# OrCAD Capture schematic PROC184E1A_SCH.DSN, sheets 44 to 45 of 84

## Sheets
44 48. DUAL PORT FTDI: size C; title: DUAL PORT FTDI; note: PROC184_SCH
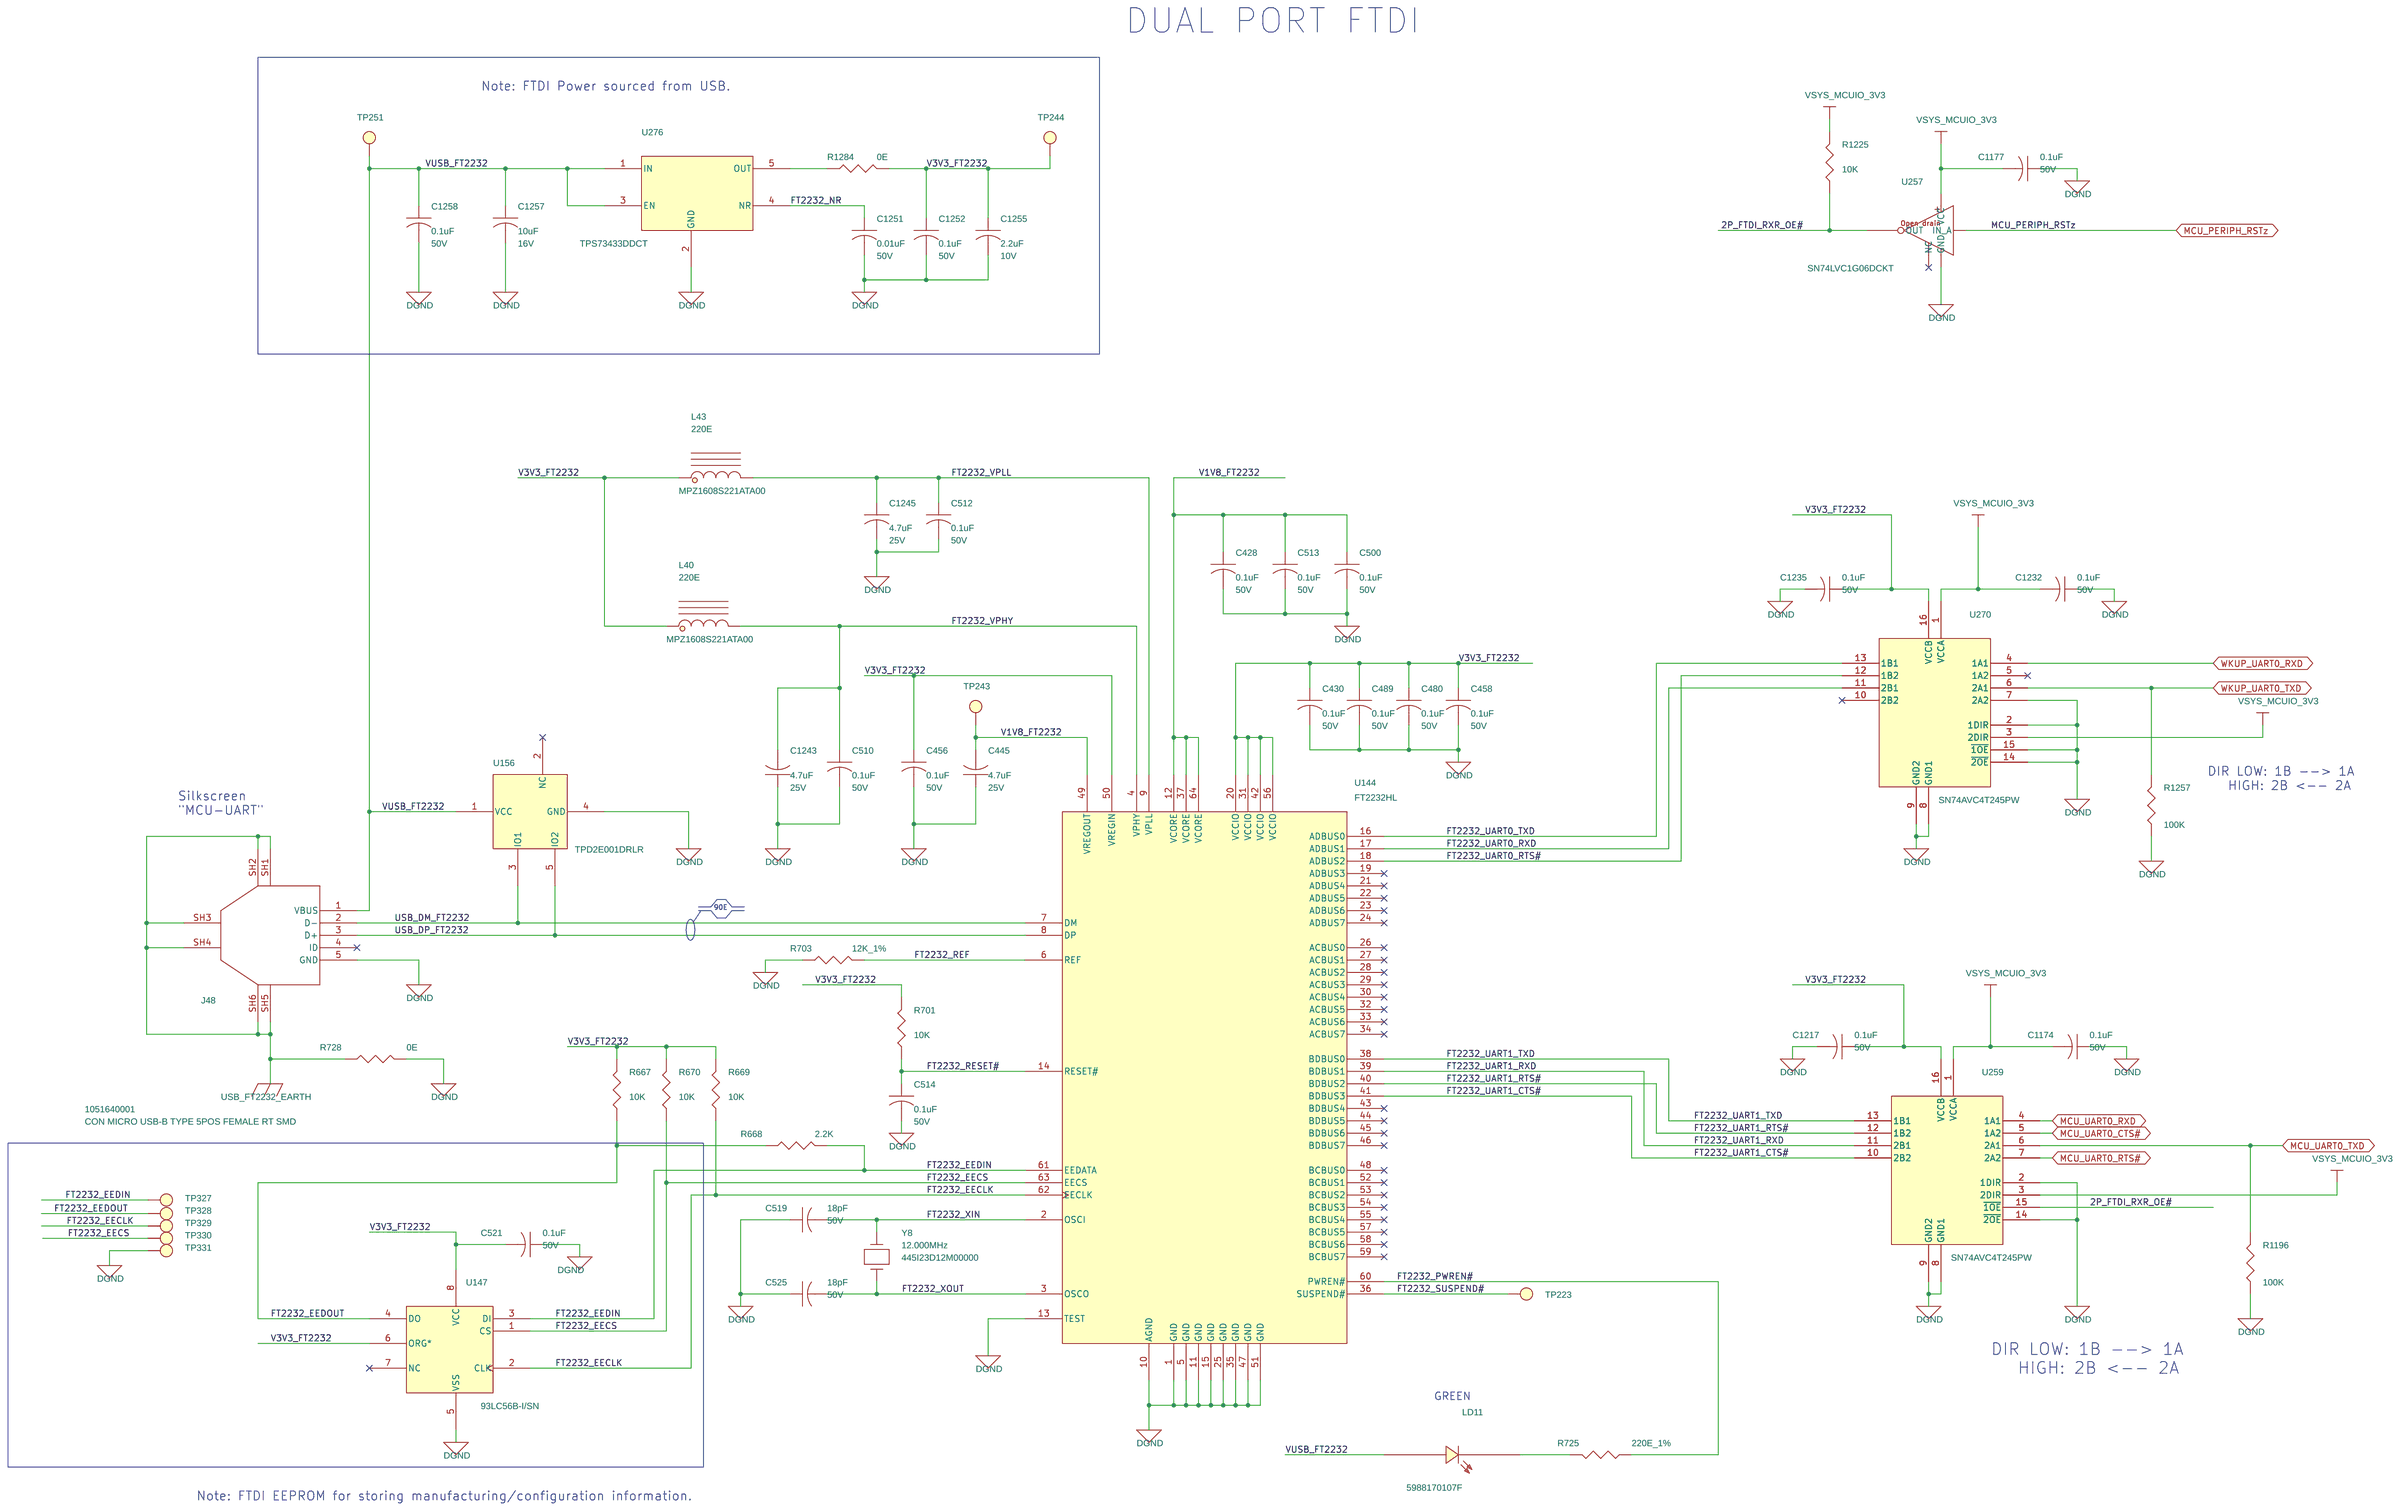
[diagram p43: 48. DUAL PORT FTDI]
45 49. QUAD PORT FTDI: size C; title: QUAD PORT FTDI; note: PROC184_SCH
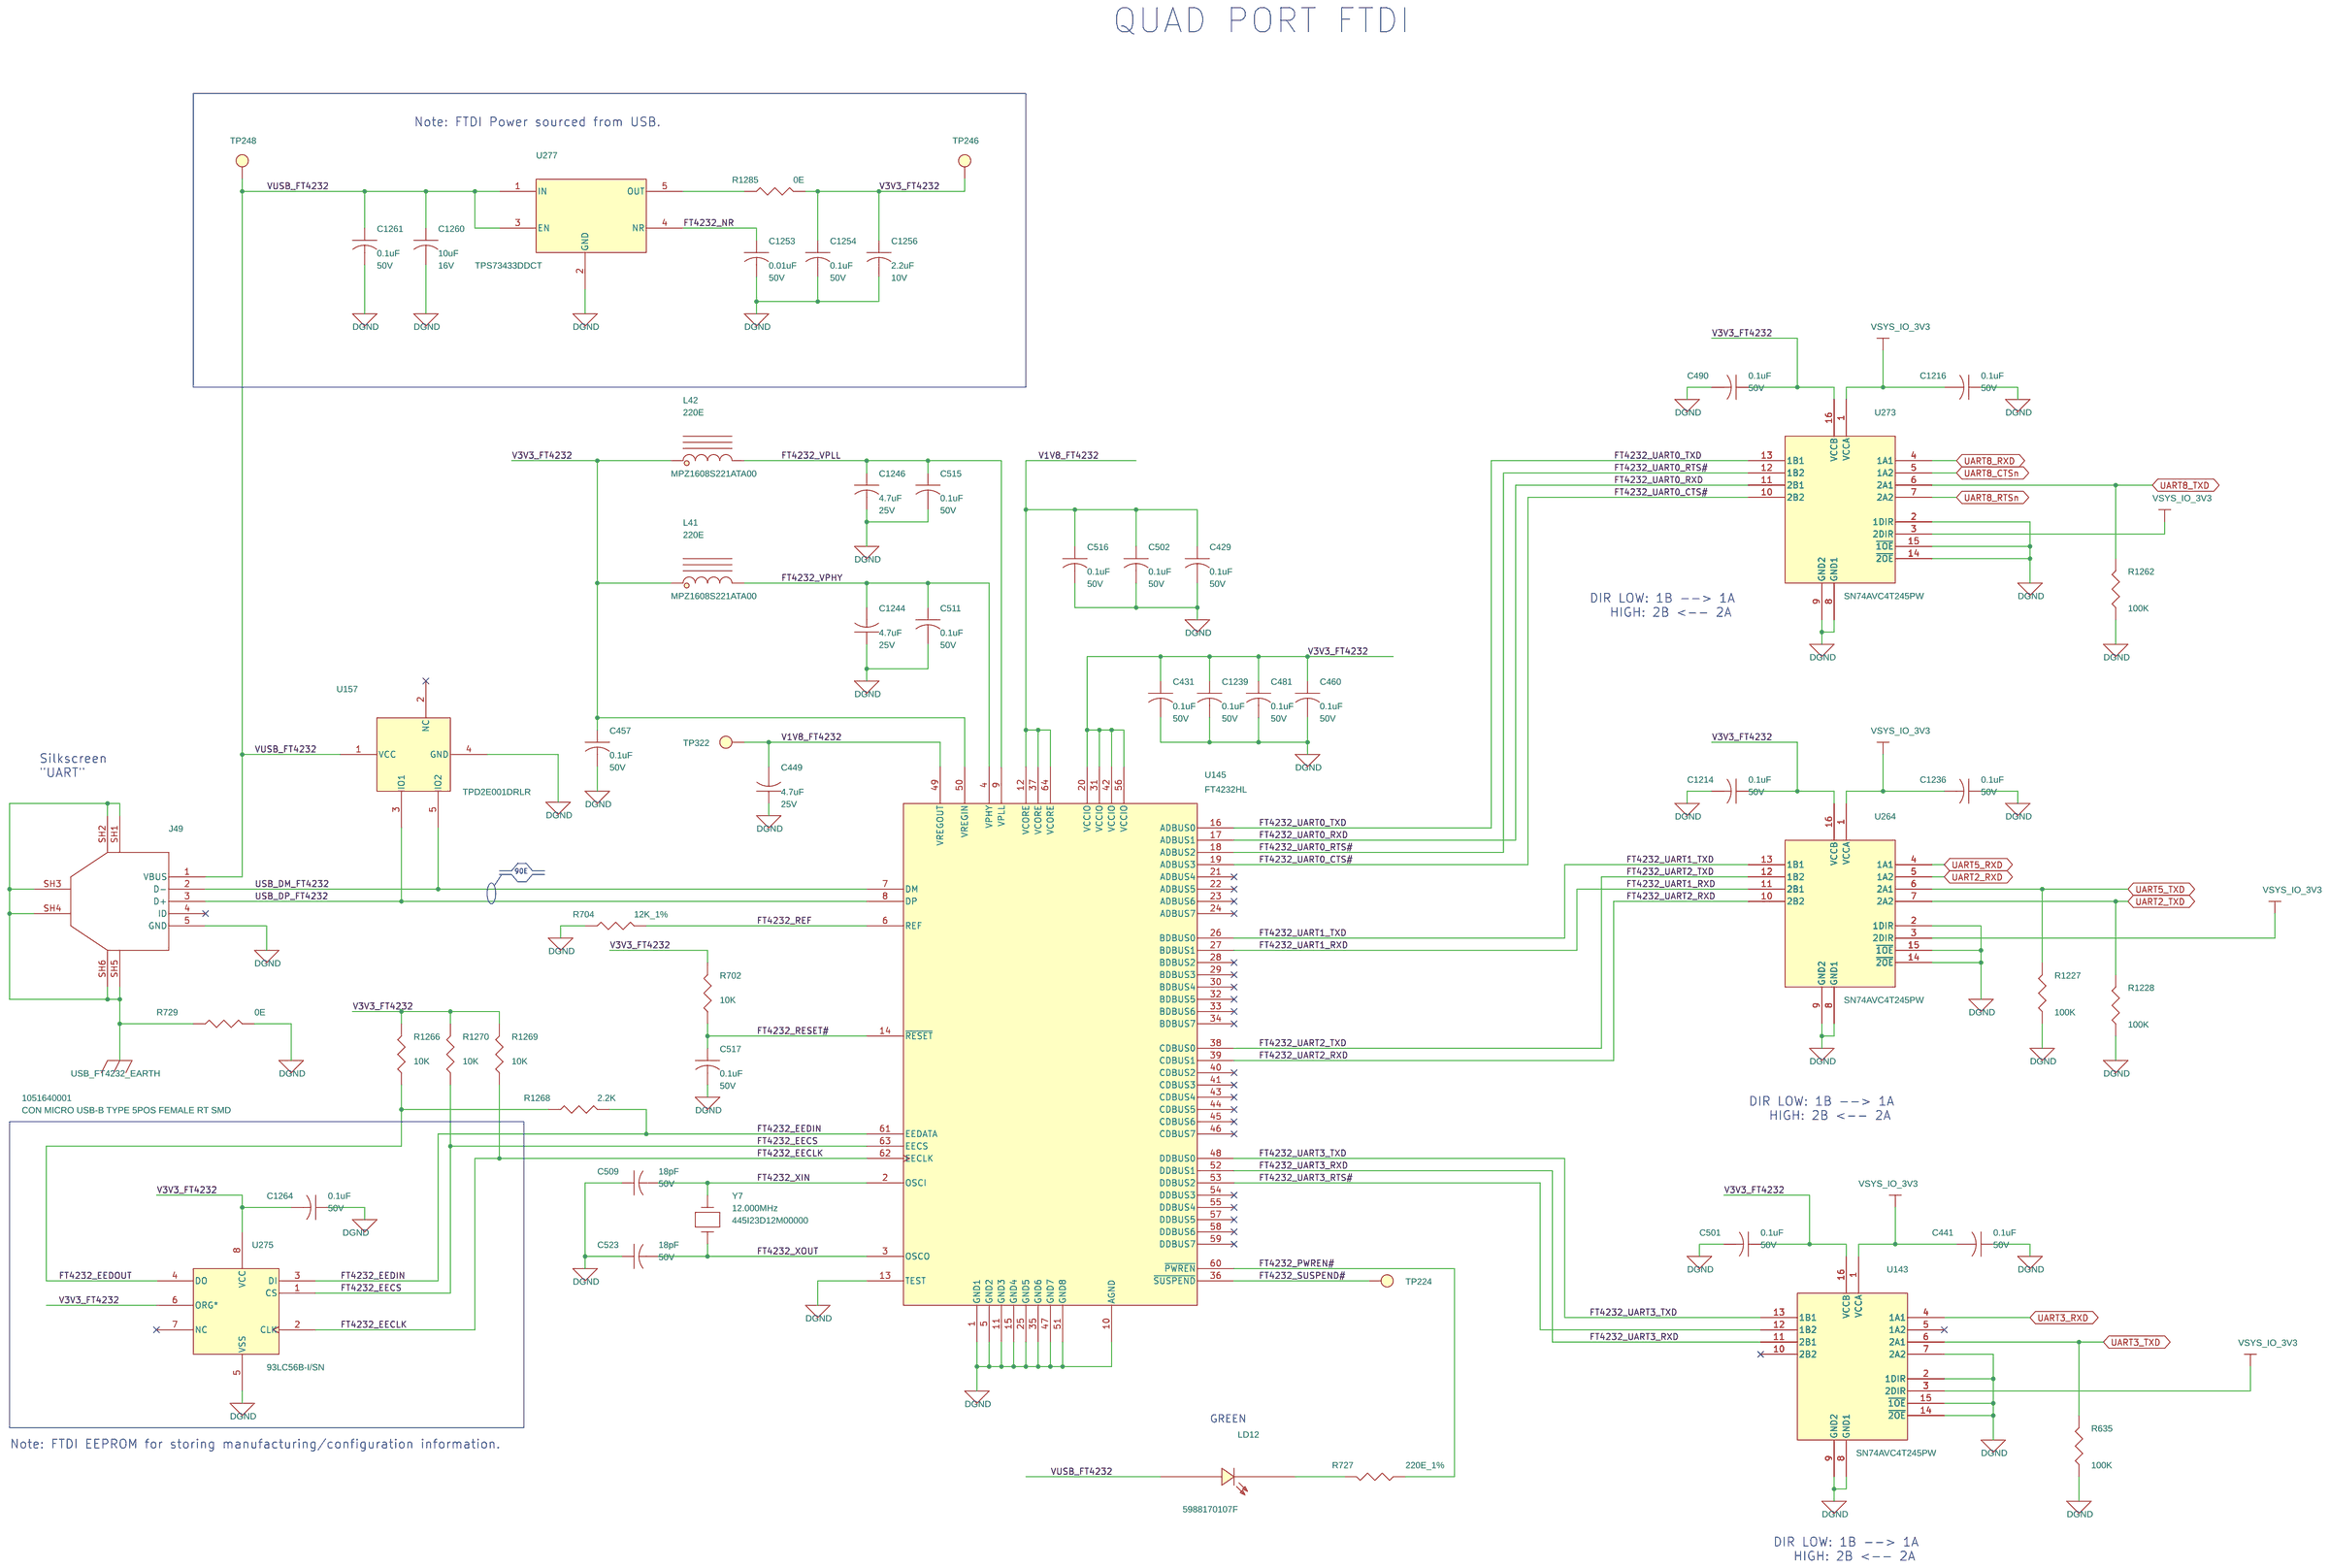
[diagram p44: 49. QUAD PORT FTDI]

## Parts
sheet 48. DUAL PORT FTDI
C428  0.1uF  [CAP0402_0-75]
C430  0.1uF  [CAP0402_0-75]
C445  4.7uF  [CAP0603_1]
C456  0.1uF  [CAP0402_0-75]
C458  0.1uF  [CAP0402_0-75]
C480  0.1uF  [CAP0402_0-75]
C489  0.1uF  [CAP0402_0-75]
C500  0.1uF  [CAP0402_0-75]
C510  0.1uF  [CAP0402_0-75]
C512  0.1uF  [CAP0402_0-75]
C513  0.1uF  [CAP0402_0-75]
C514  0.1uF  [CAP0402_0-75]
C519  18pF  [CAP0402_0-75]
C521  0.1uF  [CAP0402_0-75]
C525  18pF  [CAP0402_0-75]
C1174  0.1uF  [CAP0402_0-75]
C1177  0.1uF  [CAP0402_0-75]
C1217  0.1uF  [CAP0402_0-75]
C1232  0.1uF  [CAP0402_0-75]
C1235  0.1uF  [CAP0402_0-75]
C1243  4.7uF  [CAP0603_1]
C1245  4.7uF  [CAP0603_1]
C1251  0.01uF  [CAP0402_0-75]
C1252  0.1uF  [CAP0402_0-75]
C1255  2.2uF  [CAP0402_0-75]
C1257  10uF  [CAP0805_1-5]
C1258  0.1uF  [CAP0402_0-75]
J48  CON_MUSB-B_5_F  [CON_MUSBB5_1051640001_S_R_S_2-5]
L40  220E  [IND0603_1]
L43  220E  [IND0603_1]
LD11  5988170107F  [LED_0805_0-7]
R667  10K  [RES0402_0-5]
R668  2.2K  [RES0402_0-5]
R669  10K  [RES0402_0-5]
R670  10K  [RES0402_0-5]
R701  10K  [RES0402_0-5]
R703  12K_1%  [RES0402_0-5]
R725  220E_1%  [RES0402_0-5]
R728  0E  [RES0805_0-75]
R1196  100K  [RES0402_0-5]
R1225  10K  [RES0402_0-5]
R1257  100K  [RES0402_0-5]
R1284  0E  [RES0402_0-5]
TP223  TP30_SMD  [TP30_SMD]
TP243  THRU HOLE  [TP_40X65]
TP244  THRU HOLE  [TP_40X65]
TP251  THRU HOLE  [TP_40X65]
TP327  THRU HOLE  [TP_40X65]
TP328  THRU HOLE  [TP_40X65]
TP329  THRU HOLE  [TP_40X65]
TP330  THRU HOLE  [TP_40X65]
TP331  THRU HOLE  [TP_40X65]
U144  FT2232HL  [LQFP64_19-68_400X400_1-6]
U147  93LC56B-I/SN  [SOIC8]
U156  TPD2E001DRLR  [SOT553-5_0-6]
U257  SN74LVC1G06DCKT  [SC70-5_1-1]
U259  SN74AVC4T245PW  [TSSOP16_25-59_205X180]
U270  SN74AVC4T245PW  [TSSOP16_25-59_205X180]
U276  TPS73433DDCT  [SOT23-5_1-1]
Y8  12.000MHz  [XTAL_ABM3_205X130_SMD_1-4]
sheet 49. QUAD PORT FTDI
C429  0.1uF  [CAP0402_0-75]
C431  0.1uF  [CAP0402_0-75]
C441  0.1uF  [CAP0402_0-75]
C449  4.7uF  [CAP0603_1]
C457  0.1uF  [CAP0402_0-75]
C460  0.1uF  [CAP0402_0-75]
C481  0.1uF  [CAP0402_0-75]
C490  0.1uF  [CAP0402_0-75]
C501  0.1uF  [CAP0402_0-75]
C502  0.1uF  [CAP0402_0-75]
C509  18pF  [CAP0402_0-75]
C511  0.1uF  [CAP0402_0-75]
C515  0.1uF  [CAP0402_0-75]
C516  0.1uF  [CAP0402_0-75]
C517  0.1uF  [CAP0402_0-75]
C523  18pF  [CAP0402_0-75]
C1214  0.1uF  [CAP0402_0-75]
C1216  0.1uF  [CAP0402_0-75]
C1236  0.1uF  [CAP0402_0-75]
C1239  0.1uF  [CAP0402_0-75]
C1244  4.7uF  [CAP0603_1]
C1246  4.7uF  [CAP0603_1]
C1253  0.01uF  [CAP0402_0-75]
C1254  0.1uF  [CAP0402_0-75]
C1256  2.2uF  [CAP0402_0-75]
C1260  10uF  [CAP0805_1-5]
C1261  0.1uF  [CAP0402_0-75]
C1264  0.1uF  [CAP0402_0-75]
J49  CON_MUSB-B_5_F  [CON_MUSBB5_1051640001_S_R_S_2-5]
L41  220E  [IND0603_1]
L42  220E  [IND0603_1]
LD12  5988170107F  [LED_0805_0-7]
R635  100K  [RES0402_0-5]
R702  10K  [RES0402_0-5]
R704  12K_1%  [RES0402_0-5]
R727  220E_1%  [RES0402_0-5]
R729  0E  [RES0805_0-75]
R1227  100K  [RES0402_0-5]
R1228  100K  [RES0402_0-5]
R1262  100K  [RES0402_0-5]
R1266  10K  [RES0402_0-5]
R1268  2.2K  [RES0402_0-5]
R1269  10K  [RES0402_0-5]
R1270  10K  [RES0402_0-5]
R1285  0E  [RES0402_0-5]
TP224  TP30_SMD  [TP30_SMD]
TP246  THRU HOLE  [TP_40X65]
TP248  THRU HOLE  [TP_40X65]
TP322  TP30_SMD  [TP30_SMD]
U143  SN74AVC4T245PW  [TSSOP16_25-59_205X180]
U145  FT4232HL  [LQFP64_19-68_390X390_1-6]
U157  TPD2E001DRLR  [SOT553-5_0-6]
U264  SN74AVC4T245PW  [TSSOP16_25-59_205X180]
U273  SN74AVC4T245PW  [TSSOP16_25-59_205X180]
U275  93LC56B-I/SN  [SOIC8]
U277  TPS73433DDCT  [SOT23-5_1-1]
Y7  12.000MHz  [XTAL_ABM3_205X130_SMD_1-4]

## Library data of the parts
C428-C431 C441 C456-C458 C460 C480 C481 C489 C490 C500-C502 C510-C517 C521 C1174 C1177 C1214 C1216 C1217 C1232 C1235 C1236 C1239 C1252 C1254 C1258 C1261 C1264 = CAP: CAP CERAMIC 0.1uF 50V 10% X7R 0402; Automotive Alternate_mfr_name: TDK; Automotive Alternate_mfr_part_number: CGA2B3X7R1H104K050BB; Chkd/date: MANIRAJA/261020; Crtd /date: ALVY/211020; Custom_Duty: 15%; Customs_HS_Code: 85322990; Direct Alternate_mfr_name: TDK; Direct Alternate_mfr_part_number: C1005X7R1H104K050BE; Distributor_name: DIGIKEY; Distributor_part_number: 490-10700-1-ND; Footprint Path: Y:\MIS_DATABASE\Library\ALTIUM_TOOL\PCB_FOOTPRINTS\Altium_Footprint_Lib.PcbLib; Height: 0.55MM; Library Path: Y:\MIS_DATABASE\Library\ALTIUM_TOOL\SCHEMATICS_PARTS\MS_DISCRETE_Library.schlib; Manufacturer: MURATA; Mfr_name: MURATA; Mfr_part_number: GRM155R71H104KE14D; Mistral Part No: 120011100014-R; Package: 0402; Part_type: CAPACITORS\CERAMIC; Project: J7_CP; RoHS: RoHS; Temperature: -55°C+125°C; Tolerance: 10%; Voltage: 50V; Wattage: NA; Weight: 3.1mg; Datasheet: Y:\MIS_DATABASE\DATASHEETS\CAPACITORS\GRM155R71H104KE14.PDF
C445 C449 C1243-C1246 = CAP: CAP CERAMIC 4.7uF 25V 10% X6S 0603; Chkd/date: MANIRAJA/241018; Crtd /date: ALVY/241018; Custom_Duty: 15%; Customs_HS_Code: 85322990; Direct Alternate_mfr_name: MURATA; Direct Alternate_mfr_part_number: GRM188C81E475ME11D; Distributor_name: DIGIKEY; Distributor_part_number: 490-7199-1-ND; Footprint Path: Y:\MIS_DATABASE\Library\ALTIUM_TOOL\PCB_FOOTPRINTS\Altium_Footprint_Lib.PcbLib; Height: 1.00MM; Library Path: Y:\MIS_DATABASE\Library\ALTIUM_TOOL\SCHEMATICS_PARTS\MS_DISCRETE_Library.schlib; Manufacturer: MURATA; Mfr_name: MURATA; Mfr_part_number: GRM188C81E475KE11D; Mistral Part No: 120018100056-R; Package: 0603; Part_type: CAPACITORS\CERAMIC; Project: TI_J7ES_EVM_CP; RoHS: RoHS; Temperature: -55°C+105°C; Tolerance: 10%; Voltage: 25V; Wattage: NA; Weight: 6.3mg; Datasheet: Y:\MIS_DATABASE\DATASHEETS\CAPACITORS\GRM188C81E475KE11D.PDF
C509 C519 C523 C525 = CAP: CAP CERAMIC 18pF 50V 5% HI-Q C0G(NP0) 0402; Automotive Alternate_mfr_name: TDK; Automotive Alternate_mfr_part_number: CGA2B2C0G1H180J050BA; Chkd/date: VASANTHA/030315; Crtd /date: NAVEED/271014; Custom_Duty: 15%; Customs_HS_Code: 85322990; Direct Alternate_mfr_name: KEMET; Direct Alternate_mfr_part_number: CBR04C180J5GAC; Distributor_name: DIGIKEY; Distributor_part_number: 490-3119-1-ND; Footprint Path: Y:\MIS_DATABASE\Library\ALTIUM_TOOL\PCB_FOOTPRINTS\Altium_Footprint_Lib.PcbLib; Height: 0.55MM; Library Path: Y:\MIS_DATABASE\Library\ALTIUM_TOOL\SCHEMATICS_PARTS\MS_DISCRETE_Library.schlib; Manufacturer: MURATA; Mfr_name: MURATA; Mfr_part_number: GJM1555C1H180JB01D; Mistral Part No: 120014100019-R; Package: 0402; Part_type: CAPACITORS\CERAMIC; Project: DC_MIST_RDC; RoHS: RoHS; Temperature: -55°C+125°C; Tolerance: 5%; Voltage: 50V; Wattage: NA; Weight: 6mg; Datasheet: Y:\MIS_DATABASE\DATASHEETS\CAPACITORS\MURATA-GXX-SER_NOV17.PDF
C1251 C1253 = CAP: CAP CERAMIC 0.01uF 50V 10% X7R 0402; Automotive Alternate_mfr_name: TDK; Automotive Alternate_mfr_part_number: CGA2B2X7R1E103K050BA; Chkd/date: MANIRAJA/280319; Crtd /date: MANIRAJA/280319; Custom_Duty: 15%; Customs_HS_Code: 85322990; Direct Alternate_mfr_name: YAGEO AMERICA; Direct Alternate_mfr_part_number: CC0402KRX7R8BB103; Distributor_name: DIGIKEY; Distributor_part_number: 490-4516-1-ND; Footprint Path: Y:\MIS_DATABASE\Library\ALTIUM_TOOL\PCB_FOOTPRINTS\Altium_Footprint_Lib.PcbLib; Height: 0.55MM; Library Path: Y:\MIS_DATABASE\Library\ALTIUM_TOOL\SCHEMATICS_PARTS\MS_DISCRETE_Library.schlib; Manufacturer: MURATA; Mfr_name: MURATA; Mfr_part_number: GRM155R71H103KA88D; Mistral Part No: 120009030025-R; Package: 0402; Part_type: CAPACITORS\CERAMIC; Project: G4_SVGA; RoHS: RoHS; Temperature: -55°C+125°C; Tolerance: 10%; Voltage: 50V; Wattage: NA; Weight: 0.65mg; Datasheet: Y:\MIS_DATABASE\DATASHEETS\CAPACITORS\GRM155R71H103KA88D.PDF
C1255 C1256 = CAP: CAP CERAMIC 2.2uF 10V 10% X5R 0402; Automotive Alternate_mfr_name: TAIYO YUDEN; Automotive Alternate_mfr_part_number: LMK105ABJ225MVHF; Chkd/date: MANIRAJA/251120; Crtd /date: ALVY/241120; Custom_Duty: 15%; Customs_HS_Code: 85322990; Direct Alternate_mfr_name: TDK; Direct Alternate_mfr_part_number: C1005X5R1A225K050BC; Distributor_name: MOUSER; Distributor_part_number: 81-GRM155R61A225K01D; Footprint Path: Y:\MIS_DATABASE\Library\ALTIUM_TOOL\PCB_FOOTPRINTS\Altium_Footprint_Lib.PcbLib; Height: 0.55MM; Library Path: Y:\MIS_DATABASE\Library\ALTIUM_TOOL\SCHEMATICS_PARTS\MS_DISCRETE_Library.schlib; Manufacturer: MURATA; Mfr_name: MURATA; Mfr_part_number: GRM155R61A225KE01D; Mistral Part No: 120011100038-R; Package: 0402; Part_type: CAPACITORS\CERAMIC; Project: PLCC_DIGITAL BRD PROTO; RoHS: RoHS; Temperature: -55°C+85°C; Tolerance: 10%; Voltage: 10V; Wattage: NA; Weight: 1.6mg; Datasheet: Y:\MIS_DATABASE\DATASHEETS\CAPACITORS\MURATA-GXX-SER_NOV17.PDF
C1257 C1260 = CAP: CAP CERAMIC 10uF 16V 10% X5R 0805; Automotive Alternate_mfr_name: TDK; Automotive Alternate_mfr_part_number: CGA4J1X7S1C106K125AC; Chkd/date: SHREESHAIL/220506; Crtd /date: MAZHAR/150506; Custom_Duty: 15%; Customs_HS_Code: 85322990; Direct Alternate_mfr_name: TDK; Direct Alternate_mfr_part_number: C2012X7S1C106K125AC; Distributor_name: DIGIKEY; Distributor_part_number: 490-3886-1-ND; Footprint Path: Y:\MIS_DATABASE\Library\ALTIUM_TOOL\PCB_FOOTPRINTS\Altium_Footprint_Lib.PcbLib; Height: 1.35MM; Library Path: Y:\MIS_DATABASE\Library\ALTIUM_TOOL\SCHEMATICS_PARTS\MS_DISCRETE_Library.schlib; Manufacturer: MURATA; Mfr_name: MURATA; Mfr_part_number: GRM21BR61C106KE15L; Mistral Part No: 120009030205-R; Package: 0805; Part_type: CAPACITORS\CERAMIC; Project: VOCERA; RoHS: RoHS; Temperature: -55°C+85°C; Tolerance: 10%; Voltage: 16V; Wattage: NA; Weight: 9.5mg; Datasheet: Y:\MIS_DATABASE\DATASHEETS\CAPACITORS\MURATA-GXX-SER_NOV17.PDF
J48 J49 = CON_MUSB-B_5_1051640001: CON MICRO USB-B TYPE 5POS FEMALE RT SMD; Chkd/date: MANIRAJA/230817; Crtd /date: MANIRAJA/230817; Custom_Duty: 24%; Customs_HS_Code: 85369090; Distributor_name: DIGIKEY; Distributor_part_number: WM11263CT-ND; Height: 2.45MM; Manufacturer: MOLEX; Mfr_name: MOLEX; Mfr_part_number: 1051640001; Mistral Part No: 150017080018-R; Package: SMD; Part_type: CONNECTOR\USB; Project: TI_MAXIE_CPB; RoHS: RoHS; Temperature: -35°C+85°C; Tolerance: NA; Voltage: NA; Wattage: NA; Weight: 234mg; Datasheet: Y:\MIS_DATABASE\DATASHEETS\CONNECTORS\1051640001.PDF
L40-L43 = INDUCTOR_FERRITE: IND BEAD CHIP 220E 2.2A 25% 0603; Automotive Alternate_mfr_name: TDK; Automotive Alternate_mfr_part_number: MPZ1608S221ATD25; Chkd/date: MANIRAJA/130917; Crtd /date: USMAN/201108; Custom_Duty: 24%; Customs_HS_Code: 85437099; Direct Alternate_mfr_name: TDK; Direct Alternate_mfr_part_number: MPZ1608S221ATA00; Distributor_name: DIGIKEY; Distributor_part_number: 445-1565-1-ND; Height: 0.95MM; Manufacturer: TDK CORPORATION; Mfr_name: TDK CORPORATION; Mfr_part_number: MPZ1608S221ATA00; Mistral Part No: 130009030553-R; Package: 0603; Part_type: INDUCTOR; Project: KHAN_HSST; RoHS: RoHS; Temperature: -55°C+125°C; Tolerance: 25%; Voltage: NA; Wattage: NA; Weight: 4mg; Datasheet: Y:\MIS_DATABASE\DATASHEETS\DISCRETES\INDUCTORS\MPZ1608.PDF
LD11 LD12 = LED_598-8170-107F: LED ALINGAP GREEN CLEAR 0805; Chkd/date: MANIRAJA/230817; Crtd /date: SARANYA/070514; Custom_Duty: 24%; Customs_HS_Code: 85437099; Distributor_name: DIGIKEY; Distributor_part_number: 350-2044-1-ND; Footprint Path: Y:\MIS_DATABASE\Library\ALTIUM_TOOL\PCB_FOOTPRINTS\Altium_Footprint_Lib.PcbLib; Height: 0.70MM; Manufacturer: DIALIGHT; Mfr_name: DIALIGHT; Mistral Part No: 130014050065-R; Package: 0805; Part_type: OPTO\LED; Project: AEGIS GP BETA2; RoHS: RoHS; Temperature: -30°C+85°C; Tolerance: NA; Voltage: NA; Wattage: NA; Weight: NA; Datasheet: Y:\MIS_DATABASE\DATASHEETS\DISCRETES\LEDS\598-SER.PDF
R667 R669 R670 R701 R702 R1225 R1266 R1269 R1270 = RESISTOR: RES 10K 1/16W 5% 0402; Chkd/date: VASANTHA/061216; Crtd /date: MAZHAR/230805; Custom_Duty: 15%; Customs_HS_Code: 85332119; Distributor_name: DIGIKEY; Distributor_part_number: 311-10KJRCT-ND; Footprint Path: Y:\MIS_DATABASE\Library\ALTIUM_TOOL\PCB_FOOTPRINTS\Altium_Footprint_Lib.PcbLib; Height: 0.40MM; Library Path: Y:\MIS_DATABASE\Library\ALTIUM_TOOL\SCHEMATICS_PARTS\MS_DISCRETE_Library.schlib; Manufacturer: YAGEO AMERICA; Mfr_name: YAGEO AMERICA; Mfr_part_number: RC0402JR-0710KL; Mistral Part No: 110011060021-R; Package: 0402; Part_type: RESISTORS\FIXED; Project: HSE; RoHS: RoHS; Temperature: -55°C+155°C; Tolerance: 5%; Voltage: NA; Wattage: 1/16W; Weight: 0.65mg; Datasheet: Y:\MIS_DATABASE\DATASHEETS\RESISTORS\RCXXXXL-SER_MAR18.PDF
R668 R1268 = RESISTOR: RES 2.2K 1/16W 5% 0402; Chkd/date: VASANTHA/061216; Crtd /date: BAVISH/021210; Custom_Duty: 15%; Customs_HS_Code: 85332119; Distributor_name: DIGIKEY; Distributor_part_number: 311-2.2KJRCT-ND; Footprint Path: Y:\MIS_DATABASE\Library\ALTIUM_TOOL\PCB_FOOTPRINTS\Altium_Footprint_Lib.PcbLib; Height: 0.40MM; Library Path: Y:\MIS_DATABASE\Library\ALTIUM_TOOL\SCHEMATICS_PARTS\MS_DISCRETE_Library.schlib; Manufacturer: YAGEO AMERICA; Mfr_name: YAGEO AMERICA; Mfr_part_number: RC0402JR-072K2L; Mistral Part No: 110010120018-R; Package: 0402; Part_type: RESISTORS\FIXED; Project: TE4; RoHS: RoHS; Temperature: -55°C+155°C; Tolerance: 5%; Voltage: NA; Wattage: 1/16W; Weight: 0.65mg; Datasheet: Y:\MIS_DATABASE\DATASHEETS\RESISTORS\RCXXXXL-SER_MAR18.PDF
R703 R704 = RESISTOR: RES 12K 1/10W 1% 0402; Chkd/date: VASANTHA/041215; Crtd /date: VASANTHA/041215; Custom_Duty: 15%; Customs_HS_Code: 85332119; Distributor_name: DIGIKEY; Distributor_part_number: P12.0KLCT-ND; Footprint Path: Y:\MIS_DATABASE\Library\ALTIUM_TOOL\PCB_FOOTPRINTS\Altium_Footprint_Lib.PcbLib; Height: 0.40MM; Library Path: Y:\MIS_DATABASE\Library\ALTIUM_TOOL\SCHEMATICS_PARTS\MS_DISCRETE_Library.schlib; Manufacturer: PANASONIC-ECG; Mfr_name: PANASONIC-ECG; Mfr_part_number: ERJ-2RKF1202X; Mistral Part No: 110019040053-R; Package: 0402; Part_type: RESISTORS\FIXED; Project: TI_C5545; RoHS: RoHS; Temperature: -55°C+155°C; Tolerance: 1%; Voltage: NA; Wattage: 1/10W; Weight: 0.8mg; Datasheet: Y:\MIS_DATABASE\DATASHEETS\RESISTORS\PAN-ERJSER_NOV17.PDF
R725 R727 = RESISTOR: RES 220E 1/16W 1% 0402; Chkd/date: MANIRAJA/130917; Crtd /date: MANIRAJA/130917; Custom_Duty: 15%; Customs_HS_Code: 85332119; Distributor_name: DIGIKEY; Distributor_part_number: 311-220LRCT-ND; Footprint Path: Y:\MIS_DATABASE\Library\ALTIUM_TOOL\PCB_FOOTPRINTS\Altium_Footprint_Lib.PcbLib; Height: 0.40MM; Library Path: Y:\MIS_DATABASE\Library\ALTIUM_TOOL\SCHEMATICS_PARTS\MS_DISCRETE_Library.schlib; Manufacturer: YAGEO AMERICA; Mfr_name: YAGEO AMERICA; Mfr_part_number: RC0402FR-07220RL; Mistral Part No: 110019040169-R; Package: 0402; Part_type: RESISTORS\FIXED; Project: TI_SVB_MAXWELL_DUT; RoHS: RoHS; Temperature: -55°C+155°C; Tolerance: 1%; Voltage: NA; Wattage: 1/16W; Weight: 0.65mg; Datasheet: Y:\MIS_DATABASE\DATASHEETS\RESISTORS\RCXXXXL-SER_MAR18.PDF
R728 R729 = RESISTOR: RES 0E 1/8W 5% 0805; Chkd/date: VASANTHA/130416; Crtd /date: JEBRAN/020316; Custom_Duty: 15%; Customs_HS_Code: 85332119; Distributor_name: DIGIKEY; Distributor_part_number: 311-0.0ARCT-ND; Footprint Path: Y:\MIS_DATABASE\Library\ALTIUM_TOOL\PCB_FOOTPRINTS\Altium_Footprint_Lib.PcbLib; Height: 0.60MM; Library Path: Y:\MIS_DATABASE\Library\ALTIUM_TOOL\SCHEMATICS_PARTS\MS_DISCRETE_Library.schlib; Manufacturer: YAGEO AMERICA; Mfr_name: YAGEO AMERICA; Mfr_part_number: RC0805JR-070RL; Mistral Part No: 110009030074-R; Package: 0805; Part_type: RESISTORS\FIXED; Project: ZK_BIOMETRIC; RoHS: RoHS; Temperature: -55°C+155°C; Tolerance: 5%; Voltage: NA; Wattage: 1/8W; Weight: 5.5mg; Datasheet: Y:\MIS_DATABASE\DATASHEETS\RESISTORS\RCXXXXL-SER_MAR18.PDF
R635 R1196 R1227 R1228 R1257 R1262 = RESISTOR: RES 100K 1/10W 5% 0402; Chkd/date: VASANTHA/291216; Crtd /date: GEETHA/190406; Custom_Duty: 15%; Customs_HS_Code: 85332119; Distributor_name: DIGIKEY; Distributor_part_number: P100KJCT-ND; Footprint Path: Y:\MIS_DATABASE\Library\ALTIUM_TOOL\PCB_FOOTPRINTS\Altium_Footprint_Lib.PcbLib; Height: 0.40MM; Library Path: Y:\MIS_DATABASE\Library\ALTIUM_TOOL\SCHEMATICS_PARTS\MS_DISCRETE_Library.schlib; Manufacturer: PANASONIC-ECG; Mfr_name: PANASONIC-ECG; Mfr_part_number: ERJ-2GEJ104X; Mistral Part No: 110009030177-R; Package: 0402; Part_type: RESISTORS\FIXED; Project: RED EYE; RoHS: RoHS; Temperature: -55°C+155°C; Tolerance: 5%; Voltage: NA; Wattage: 1/10W; Weight: 0.8mg; Datasheet: Y:\MIS_DATABASE\DATASHEETS\RESISTORS\PAN-ERJSER_NOV17.PDF
R1284 R1285 = RESISTOR: RES 0E 1/10W JUMPER 0402; Chkd/date: VASANTHA/061216; Crtd /date: NAVEED/201014; Custom_Duty: 15%; Customs_HS_Code: 85332119; Distributor_name: DIGIKEY; Distributor_part_number: P0.0JCT-ND; Footprint Path: Y:\MIS_DATABASE\Library\ALTIUM_TOOL\PCB_FOOTPRINTS\Altium_Footprint_Lib.PcbLib; Height: 0.40MM; IBISSP_MODLES: VALUE REPEATING 2 TIME; Library Path: Y:\MIS_DATABASE\Library\ALTIUM_TOOL\SCHEMATICS_PARTS\MS_DISCRETE_Library.schlib; Manufacturer: PANASONIC-ECG; Mfr_name: PANASONIC-ECG; Mfr_part_number: ERJ-2GE0R00X; Mistral Part No: 110018030052-R; Package: 0402; Part_type: RESISTORS\FIXED; Project: AEGIS POM; RoHS: RoHS; Temperature: -55°C+155°C; Tolerance: NA; Voltage: NA; Wattage: 1/10W; Weight: 0.8mg; Datasheet: Y:\MIS_DATABASE\DATASHEETS\RESISTORS\PAN-ERJSER_NOV17.PDF
TP223 TP224 TP322 = TESTPOINT: TESTPOINT CIR 30 SMD; Chkd/date: SHREESHAIL/171006; Crtd /date: MAZHAR/171006; Custom_Duty: NA; Customs_HS_Code: NA; Distributor_name: NA; Distributor_part_number: NA; Footprint Path: Y:\MIS_DATABASE\Library\ALTIUM_TOOL\PCB_FOOTPRINTS\Altium_Footprint_Lib.PcbLib; Height: NA; Library Path: Y:\MIS_DATABASE\Library\ALTIUM_TOOL\SCHEMATICS_PARTS\MS_DISCRETE_Library.schlib; MECHANICAL 3D STEP FILE: NA; Manufacturer: LOCAL; Mfr_name: LOCAL; Mistral Part No: 130009030930; Package: SMD; Project: BT MODULE_CSRBC04; RoHS: NA; Temperature: NA; Tolerance: NA; Voltage: NA; Wattage: NA; Weight: NA; Datasheet: NA
TP243 TP244 TP246 TP248 TP251 TP327-TP331 = TESTPOINT: TESTPOINT 1.0MM DRILL PTH; Chkd/date: MAZHAR/271211; Crtd /date: SHREESHAIL/041005; Distributor_name: NA; Distributor_part_number: NA; Height: NA; Manufacturer: LOCAL; Mfr_name: LOCAL; Mistral Part No: 130009030938; Package: THRU-HOLE; Project: HSE; Datasheet: NA
U144 = FT2232H_LQFP64_TI: IC DUAL HIGH SPEED USB TO MULTIPURPOSE FIFO LQFP64; Chkd/date: BALACHANDAR/150514; Crtd /date: SARANYA/140514; Custom_Duty: 15%; Customs_HS_Code: 85423100; Distributor_name: DIGIKEY; Distributor_part_number: 768-1024-1-ND; Footprint Path: Y:\MIS_DATABASE\Library\ALTIUM_TOOL\PCB_FOOTPRINTS\Altium_Footprint_Lib.PcbLib; Height: 1.60MM; Library Path: Y:\MIS_DATABASE\Library\ALTIUM_TOOL\SCHEMATICS_PARTS\MS_TELECOM_Library.schlib; Library Ref: FT2232H_LQFP64; Manufacturer: FTDI; Mfr_name: FTDI; Mfr_part_number: FT2232HL-REEL; Mistral Part No: 143014050006-R; Package: LQFP64; Part_type: ICS\TELECOM\UART; Project: AEGIS GP BETA2; RoHS: RoHS; Temperature: -40°C+85°C; Tolerance: NA; Voltage: NA; Wattage: NA; Weight: NA; Datasheet: Y:\MIS_DATABASE\DATASHEETS\ICS\MEMORY\FT2232H_SERIES.PDF
U147 U275 = 93LC56B-I_SN_SOIC8: IC 2K MICRPWIRE COMPATIBLE SERIAL EEPROM SOIC8; Chkd/date: BALACHANDAR/160514; Crtd /date: SARANYA/140514; Custom_Duty: 15%; Customs_HS_Code: 85423100; Distributor_name: DIGIKEY; Distributor_part_number: 93LC56B-I/SN-ND; Height: 1.750MM; Library Ref: 93LC56B-I/SN_SOIC8; Manufacturer: MICROCHIP; Mfr_name: MICROCHIP; Mistral Part No: 141114050005-R; Part_type: ICS\DIGITAL\MEMORY; Project: AEGIS GP BETA2; RoHS: RoHS; Temperature: -40°C+85°C; Tolerance: NA; Voltage: NA; Wattage: NA; Weight: NA; Datasheet: Y:\MIS_DATABASE\DATASHEETS\ICS\MEMORY\93LC56B.PDF
U156 U157 = TPD2E001DRLR_SOT-5: IC ESD-PROTECTION DIODE ARRAYS SOT-5; Chkd/date: NAVEED/150714; Crtd /date: MUDDU/250510; Custom_Duty: 15%; Customs_HS_Code: 85423100; Distributor_name: DIGIKEY; Distributor_part_number: 296-21883-1-ND; Footprint Path: Y:\MIS_DATABASE\Library\ALTIUM_TOOL\PCB_FOOTPRINTS\Altium_Footprint_Lib.PcbLib; Height: 0.60MM; Library Path: Y:\MIS_DATABASE\Library\ALTIUM_TOOL\SCHEMATICS_PARTS\MS_FILTER_Library.schlib; Manufacturer: TEXAS INSTRUMENTS; Mfr_name: TEXAS INSTRUMENTS; Mistral Part No: 140110060007-R; Package: SOT-5; Part_type: ICS\ANALOG\ACTIVE FILTER; Project: CENTAURUS; RoHS: RoHS; Temperature: -40°C+85°C; Tolerance: NA; Voltage: NA; Wattage: NA; Weight: 2.8mg; Datasheet: Y:\MIS_DATABASE\DATASHEETS\ICS\MISC\TPD2E001DRLR.PDF
U257 = SN74LVC1G06DCKT_SC70-5: IC SINGLE INVERTER BUFFER/DRIVER WITH OPEN-DRAIN OUTPUT SC70-5; Chkd/date: VASANTHA/280616; Crtd /date: MAZHAR/170107; Custom_Duty: 15%; Customs_HS_Code: 85423100; Distributor_name: DIGIKEY; Distributor_part_number: 296-32290-1-ND; Footprint Path: Y:\MIS_DATABASE\Library\ALTIUM_TOOL\PCB_FOOTPRINTS\Altium_Footprint_Lib.PcbLib; Height: 1.10MM; Junction to Board °C/W: 70.9; Junction to Case °C/W: 178.9; Library Path: Y:\MIS_DATABASE\Library\ALTIUM_TOOL\SCHEMATICS_PARTS\MS_COMBINATIONAL_Library.schlib; Manufacturer: TEXAS INSTRUMENTS; Mfr_name: TEXAS INSTRUMENTS; Mistral Part No: 141009030132-R; Package: SC70-5; Part_type: ICS\DIGITAL\COMBINATIONAL; Project: OMAP2430_OSK; RoHS: RoHS; Temperature: -40°C+125°C; Tolerance: NA; Voltage: NA; Wattage: NA; Weight: 20mg; Datasheet: Y:\MIS_DATABASE\DATASHEETS\ICS\DIGITAL\COMBINATIONAL\SN74LVC1G06-SER.PDF
U143 U259 U264 U270 U273 = SN74AVC4T245PW_TSSOP16: IC 4-BIT DUAL SUPPLY BUS TRANSCEIVER TSSOP16; Chkd/date: SHREESHAIL/030506; Crtd /date: MAZHAR/270406; Custom_Duty: 15%; Customs_HS_Code: 85423100; Distributor_name: MOUSER; Distributor_part_number: 595-SN74AVC4T245PW; Height: 1.20MM; Manufacturer: TEXAS INSTRUMENTS; Mfr_name: TEXAS INSTRUMENTS; Mistral Part No: 141009030111-R; Package: TSSOP16; Part_type: ICS\DIGITAL\COMBINATIONAL; Project: VOCERA; RoHS: Sb/ Br FREE; Datasheet: Y:\MIS_DATABASE\DATASHEETS\ICS\DIGITAL\BUSTRANSCEIVER\SN74AVC4T245.PDF
U276 U277 = TPS73028DBV_SOT23-5: IC 250mA 3.3V LOW IQ HIGH PSRR LDO LINEAR REGULATOR TSOT23-5; Automotive Alternate_mfr_name: TEXAS INSTRUMENTS; Automotive Alternate_mfr_part_number: TPS73433TDDCRQ1; Chkd/date: MANIRAJA/101018; Crtd /date: ALVY/101018; Custom_Duty: 15%; Customs_HS_Code: 85423100; Distributor_name: DIGIKEY; Distributor_part_number: 296-25164-1-ND; Footprint Path: Y:\MIS_DATABASE\Library\ALTIUM_TOOL\PCB_FOOTPRINTS\Altium_Footprint_Lib.PcbLib; Height: 1.10MM; Library Path: Y:\MIS_DATABASE\Library\ALTIUM_TOOL\SCHEMATICS_PARTS\MS_MISCPOWER_Library.schlib; Manufacturer: TEXAS INSTRUMENTS; Mfr_name: TEXAS INSTRUMENTS; Mistral Part No: 142018100007-R; Package: TSOT23-5; Part_type: ICS\POWER\VOLTAGE REGULATOR; Project: TI_J7ES_EVM_CP; RoHS: RoHS; Temperature: -40°C+125°C; Tolerance: NA; Voltage: NA; Wattage: NA; Weight: 6.3mg; Datasheet: Y:\MIS_DATABASE\DATASHEETS\MISC\REGULATORS\TPS734XX.PDF
Y7 Y8 = CRY: CRY 12.000MHz 18pF SMD; Chkd/date: MANIRAJA/310818; Crtd /date: MANIRAJA/310818; Custom_Duty: 24%; Customs_HS_Code: 85439000; Distributor_name: DIGIKEY; Distributor_part_number: CTX1170CT-ND; Footprint Path: Y:\MIS_DATABASE\Library\ALTIUM_TOOL\PCB_FOOTPRINTS\Altium_Footprint_Lib.PcbLib; Height: 1.35MM; Library Path: Y:\MIS_DATABASE\Library\ALTIUM_TOOL\SCHEMATICS_PARTS\MS_DISCRETE_Library.schlib; Manufacturer: CTS; Mfr_name: CTS; Mfr_part_number: 445I23D12M00000; Mistral Part No: 130018080040-R; Package: SMD; Part_type: CRYSTAL; Project: TI_MAXIE_CPB; RoHS: RoHS; Temperature: -40°C+85°C; Tolerance: NA; Voltage: NA; Wattage: NA; Weight: 50mg; Datasheet: Y:\MIS_DATABASE\DATASHEETS\MISC\CRY_OSC\445.PDF
U145 = FT4232H_LQFP64_TI: IC HIGH SPEED QUAD USB UART LQFP64; Chkd/date: MANIRAJA/110917; Crtd /date: VIJAYALAKSHMI/120813; Custom_Duty: 15%; Customs_HS_Code: 85423100; Distributor_name: DIGIKEY; Distributor_part_number: 768-1026-1-ND; Footprint Path: Y:\MIS_DATABASE\Library\ALTIUM_TOOL\PCB_FOOTPRINTS\Altium_Footprint_Lib.PcbLib; Height: 1.60MM; Library Path: Y:\MIS_DATABASE\Library\ALTIUM_TOOL\SCHEMATICS_PARTS\MS_COMBINATIONAL_Library.schlib; Library Ref: FT4232H_LQFP64; Manufacturer: FTDI; Mfr_name: FTDI; Mfr_part_number: FT4232HL-REEL; Mistral Part No: 141013080006-R; Package: LQFP64; Part_type: ICS\DIGITAL\PERIPHERAL; Project: DM37XX; RoHS: RoHS; Temperature: -40°C+85°C; Tolerance: NA; Voltage: NA; Wattage: NA; Weight: 342.7mg; Datasheet: Y:\MIS_DATABASE\DATASHEETS\ICS\DIGITAL\PERIPHERAL\FT4232HX.PDF

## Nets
DGND: C428.2 C429.2 C430.2 C431.2 C441.1 C445.1 C449.1 C456.2 C457.2 C458.2 C460.2 C480.2 C481.2 C489.2 C490.2 C500.2 C501.2 C502.2 C509.1 C510.2 C511.2 C512.2 C513.2 C514.2 C515.2 C516.2 C517.2 C519.1 C521.1 C523.1 C525.1 C1174.1 C1177.1 C1214.2 C1216.1 C1217.2 C1232.1 C1235.2 C1236.1 C1239.2 C1243.1 C1244.1 C1245.2 C1246.2 C1251.2 C1252.2 C1253.2 C1254.2 C1255.2 C1256.2 C1257.2 C1258.2 C1260.2 C1261.2 C1264.1 J48.5(GND) J49.5(GND) R635.1 R703.1 R704.1 R728.2 R729.2 R1196.1 R1227.1 R1228.1 R1257.1 R1262.1 TP331.1(TP) U143.2(1DIR) U143.7(2A2) U143.8(GND1) U143.9(GND2) U143.14(~{2OE}) U143.15(~{1OE}) U144.1(GND) U144.5(GND) U144.10(AGND) U144.11(GND) U144.13(TEST) U144.15(GND) U144.25(GND) U144.35(GND) U144.47(GND) U144.51(GND) U145.1(GND1) U145.5(GND2) U145.10(AGND) U145.11(GND3) U145.13(TEST) U145.15(GND4) U145.25(GND5) U145.35(GND6) U145.47(GND7) U145.51(GND8) U147.5(VSS) U156.4(GND) U157.4(GND) U257.3(GND) U259.2(1DIR) U259.8(GND1) U259.9(GND2) U259.14(~{2OE}) U264.2(1DIR) U264.8(GND1) U264.9(GND2) U264.14(~{2OE}) U264.15(~{1OE}) U270.2(1DIR) U270.7(2A2) U270.8(GND1) U270.9(GND2) U270.14(~{2OE}) U270.15(~{1OE}) U273.2(1DIR) U273.8(GND1) U273.9(GND2) U273.14(~{2OE}) U273.15(~{1OE}) U275.5(VSS) U276.2(GND) U277.2(GND) ; also on sheet 11 12 13 14 15 16 17 18 20 21 22 23 24 25 26 27 28 29 30 31 32 33 34 35 36 37 38 39 40 41 42 43 46 47 48 49 50 51 52 53 54 55 56 57 58 59 60 61 62 63 64 65 66 67 68 69 70 71 72 73 76 77 78 79 81 82 83 84
V1V8_FT2232: C428.1 C445.2 C500.1 C513.1 TP243.1(TP) U144.12(VCORE) U144.37(VCORE) U144.49(VREGOUT) U144.64(VCORE)
V1V8_FT4232: C429.1 C449.2 C502.1 C516.1 TP322.1(TP) U145.12(VCORE) U145.37(VCORE) U145.49(VREGOUT) U145.64(VCORE)
V3V3_FT2232: C430.1 C456.1 C458.1 C480.1 C489.1 C521.2 C1217.1 C1235.1 C1252.1 C1255.1 L40.1 L43.1 R667.2 R669.2 R670.2 R701.2 R1284.2 TP244.1(TP) U144.20(VCCIO) U144.31(VCCIO) U144.42(VCCIO) U144.50(VREGIN) U144.56(VCCIO) U147.6(ORG*) U147.8(VCC) U259.16(VCCB) U270.16(VCCB)
V3V3_FT4232: C431.1 C457.1 C460.1 C481.1 C490.1 C501.1 C1214.1 C1239.1 C1254.1 C1256.1 C1264.2 L41.1 L42.1 R702.2 R1266.2 R1269.2 R1270.2 R1285.2 TP246.1(TP) U143.16(VCCB) U145.20(VCCIO) U145.31(VCCIO) U145.42(VCCIO) U145.50(VREGIN) U145.56(VCCIO) U264.16(VCCB) U273.16(VCCB) U275.6(ORG*) U275.8(VCC)
2P_FTDI_RXR_OE#: R1225.1 U257.4(OUT) U259.15(~{1OE})
FT2232_EECLK: R669.1 TP329.1(TP) U144.62(EECLK) U147.2(CLK)
FT2232_EECS: R670.1 TP330.1(TP) U144.63(EECS) U147.1(CS)
FT2232_EEDIN: R668.2 TP327.1(TP) U144.61(EEDATA) U147.3(DI)
FT2232_EEDOUT: R667.1 R668.1 TP328.1(TP) U147.4(DO)
FT2232_NR: C1251.1 U276.4(NR)
FT2232_PWREN#: R725.2 U144.60(PWREN#)
FT2232_REF: R703.2 U144.6(REF)
FT2232_RESET#: C514.1 R701.1 U144.14(RESET#)
FT2232_SUSPEND#: TP223.1(TP) U144.36(SUSPEND#)
FT2232_UART0_RTS#: U144.18(ADBUS2) U270.12(1B2)
FT2232_UART0_RXD: U144.17(ADBUS1) U270.11(2B1)
FT2232_UART0_TXD: U144.16(ADBUS0) U270.13(1B1)
FT2232_UART1_CTS#: U144.41(BDBUS3) U259.10(2B2)
FT2232_UART1_RTS#: U144.40(BDBUS2) U259.12(1B2)
FT2232_UART1_RXD: U144.39(BDBUS1) U259.11(2B1)
FT2232_UART1_TXD: U144.38(BDBUS0) U259.13(1B1)
FT2232_VPHY: C510.1 C1243.2 L40.2 U144.4(VPHY)
FT2232_VPLL: C512.1 C1245.1 L43.2 U144.9(VPLL)
FT2232_XIN: C519.2 U144.2(OSCI) Y8.1
FT2232_XOUT: C525.2 U144.3(OSCO) Y8.2
FT4232_EECLK: R1269.1 U145.62(EECLK) U275.2(CLK)
FT4232_EECS: R1270.1 U145.63(EECS) U275.1(CS)
FT4232_EEDIN: R1268.2 U145.61(EEDATA) U275.3(DI)
FT4232_EEDOUT: R1266.1 R1268.1 U275.4(DO)
FT4232_NR: C1253.1 U277.4(NR)
FT4232_PWREN#: R727.2 U145.60(~{PWREN})
FT4232_REF: R704.2 U145.6(REF)
FT4232_RESET#: C517.1 R702.1 U145.14(~{RESET})
FT4232_SUSPEND#: TP224.1(TP) U145.36(~{SUSPEND})
FT4232_UART0_CTS#: U145.19(ADBUS3) U273.10(2B2)
FT4232_UART0_RTS#: U145.18(ADBUS2) U273.12(1B2)
FT4232_UART0_RXD: U145.17(ADBUS1) U273.11(2B1)
FT4232_UART0_TXD: U145.16(ADBUS0) U273.13(1B1)
FT4232_UART1_RXD: U145.27(BDBUS1) U264.11(2B1)
FT4232_UART1_TXD: U145.26(BDBUS0) U264.13(1B1)
FT4232_UART2_RXD: U145.39(CDBUS1) U264.10(2B2)
FT4232_UART2_TXD: U145.38(CDBUS0) U264.12(1B2)
FT4232_UART3_RTS#: U143.12(1B2) U145.53(DDBUS2)
FT4232_UART3_RXD: U143.11(2B1) U145.52(DDBUS1)
FT4232_UART3_TXD: U143.13(1B1) U145.48(DDBUS0)
FT4232_VPHY: C511.1 C1244.2 L41.2 U145.4(VPHY)
FT4232_VPLL: C515.1 C1246.1 L42.2 U145.9(VPLL)
FT4232_XIN: C509.2 U145.2(OSCI) Y7.1
FT4232_XOUT: C523.2 U145.3(OSCO) Y7.2
MCU_PERIPH_RSTz: U257.2(IN_A) ; also on sheet 17 18 37 62
MCU_UART0_CTS#: U259.5(1A2) ; also on sheet 18
MCU_UART0_RTS#: U259.7(2A2) ; also on sheet 18
MCU_UART0_RXD: U259.4(1A1) ; also on sheet 18
MCU_UART0_TXD: R1196.2 U259.6(2A1) ; also on sheet 18
UART2_RXD: U264.5(1A2) ; also on sheet 20
UART2_TXD: R1228.2 U264.7(2A2) ; also on sheet 20
UART3_RXD: U143.4(1A1) ; also on sheet 20
UART3_TXD: R635.2 U143.6(2A1) ; also on sheet 48
UART5_RXD: U264.4(1A1) ; also on sheet 20
UART5_TXD: R1227.2 U264.6(2A1) ; also on sheet 20
UART8_CTSn: U273.5(1A2) ; also on sheet 20
UART8_RTSn: U273.7(2A2) ; also on sheet 20
UART8_RXD: U273.4(1A1) ; also on sheet 20
UART8_TXD: R1262.2 U273.6(2A1) ; also on sheet 20
USB_DM_FT2232: J48.2(D-) U144.7(DM) U156.3(IO1)
USB_DM_FT4232: J49.2(D-) U145.7(DM) U157.5(IO2)
USB_DP_FT2232: J48.3(D+) U144.8(DP) U156.5(IO2)
USB_DP_FT4232: J49.3(D+) U145.8(DP) U157.3(IO1)
USB_FT2232_EARTH: J48.SH1 J48.SH2 J48.SH3 J48.SH4 J48.SH5 J48.SH6 R728.1
USB_FT4232_EARTH: J49.SH1 J49.SH2 J49.SH3 J49.SH4 J49.SH5 J49.SH6 R729.1
VSYS_IO_3V3: C441.2 C1216.2 C1236.2 U143.1(VCCA) U143.3(2DIR) U264.1(VCCA) U264.3(2DIR) U273.1(VCCA) U273.3(2DIR) ; also on sheet 18 20 22 24 29 30 31 32 33 35 36 37 38 40 41 42 43 46 48 50 51 53 56 57 58 59 60 61 65 66 68 75 81 82
VSYS_MCUIO_3V3: C1174.2 C1177.2 C1232.2 R1225.2 U257.5(VCC) U259.1(VCCA) U259.3(2DIR) U270.1(VCCA) U270.3(2DIR) ; also on sheet 16 17 18 21 22 23 35 36 43 48 49 55 62 65 68 75
VUSB_FT2232: C1257.1 C1258.1 J48.1(VBUS) LD11.2 TP251.1(TP) U156.1(VCC) U276.1(IN) U276.3(EN)
VUSB_FT4232: C1260.1 C1261.1 J49.1(VBUS) LD12.2 TP248.1(TP) U157.1(VCC) U277.1(IN) U277.3(EN)
WKUP_UART0_RXD: U270.4(1A1) ; also on sheet 18
WKUP_UART0_TXD: R1257.2 U270.6(2A1) ; also on sheet 18
N23190579: R1284.1 U276.5(OUT)
N23191902: LD11.1 R725.1
N23194116: R1285.1 U277.5(OUT)
N23195767: LD12.1 R727.1

Not connected (* = marked no-connect by the designer): J48 4(ID)*; J49 4(ID)*; U143 5(1A2)* 10(2B2)*; U144 19(ADBUS3)* 21(ADBUS4)* 22(ADBUS5)* 23(ADBUS6)* 24(ADBUS7)* 26(ACBUS0)* 27(ACBUS1)* 28(ACBUS2)* 29(ACBUS3)* 30(ACBUS4)* 32(ACBUS5)* 33(ACBUS6)* 34(ACBUS7)* 43(BDBUS4)* 44(BDBUS5)* 45(BDBUS6)* 46(BDBUS7)* 48(BCBUS0)* 52(BCBUS1)* 53(BCBUS2)* 54(BCBUS3)* 55(BCBUS4)* 57(BCBUS5)* 58(BCBUS6)* 59(BCBUS7)*; U145 21(ADBUS4)* 22(ADBUS5)* 23(ADBUS6)* 24(ADBUS7)* 28(BDBUS2)* 29(BDBUS3)* 30(BDBUS4)* 32(BDBUS5)* 33(BDBUS6)* 34(BDBUS7)* 40(CDBUS2)* 41(CDBUS3)* 43(CDBUS4)* 44(CDBUS5)* 45(CDBUS6)* 46(CDBUS7)* 54(DDBUS3)* 55(DDBUS4)* 57(DDBUS5)* 58(DDBUS6)* 59(DDBUS7)*; U147 7(NC)*; U156 2(NC)*; U157 2(NC)*; U257 1(NC)*; U270 5(1A2)* 10(2B2)*; U275 7(NC)*

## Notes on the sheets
sheet 44
- DUAL PORT FTDI
- Note: FTDI Power sourced from USB.
- DIR LOW: 1B --> 1A
     HIGH: 2B <-- 2A
- Silkscreen
  "MCU-UART"
- 90E
- DIR LOW: 1B --> 1A
     HIGH: 2B <-- 2A
- GREEN
- Note: FTDI EEPROM for storing manufacturing/configuration information.
sheet 45
- QUAD PORT FTDI
- Note: FTDI Power sourced from USB.
- DIR LOW: 1B --> 1A
     HIGH: 2B <-- 2A
- Silkscreen
  "UART"
- 90E
- DIR LOW: 1B --> 1A
     HIGH: 2B <-- 2A
- GREEN
- Note: FTDI EEPROM for storing manufacturing/configuration information.
- DIR LOW: 1B --> 1A
     HIGH: 2B <-- 2A
